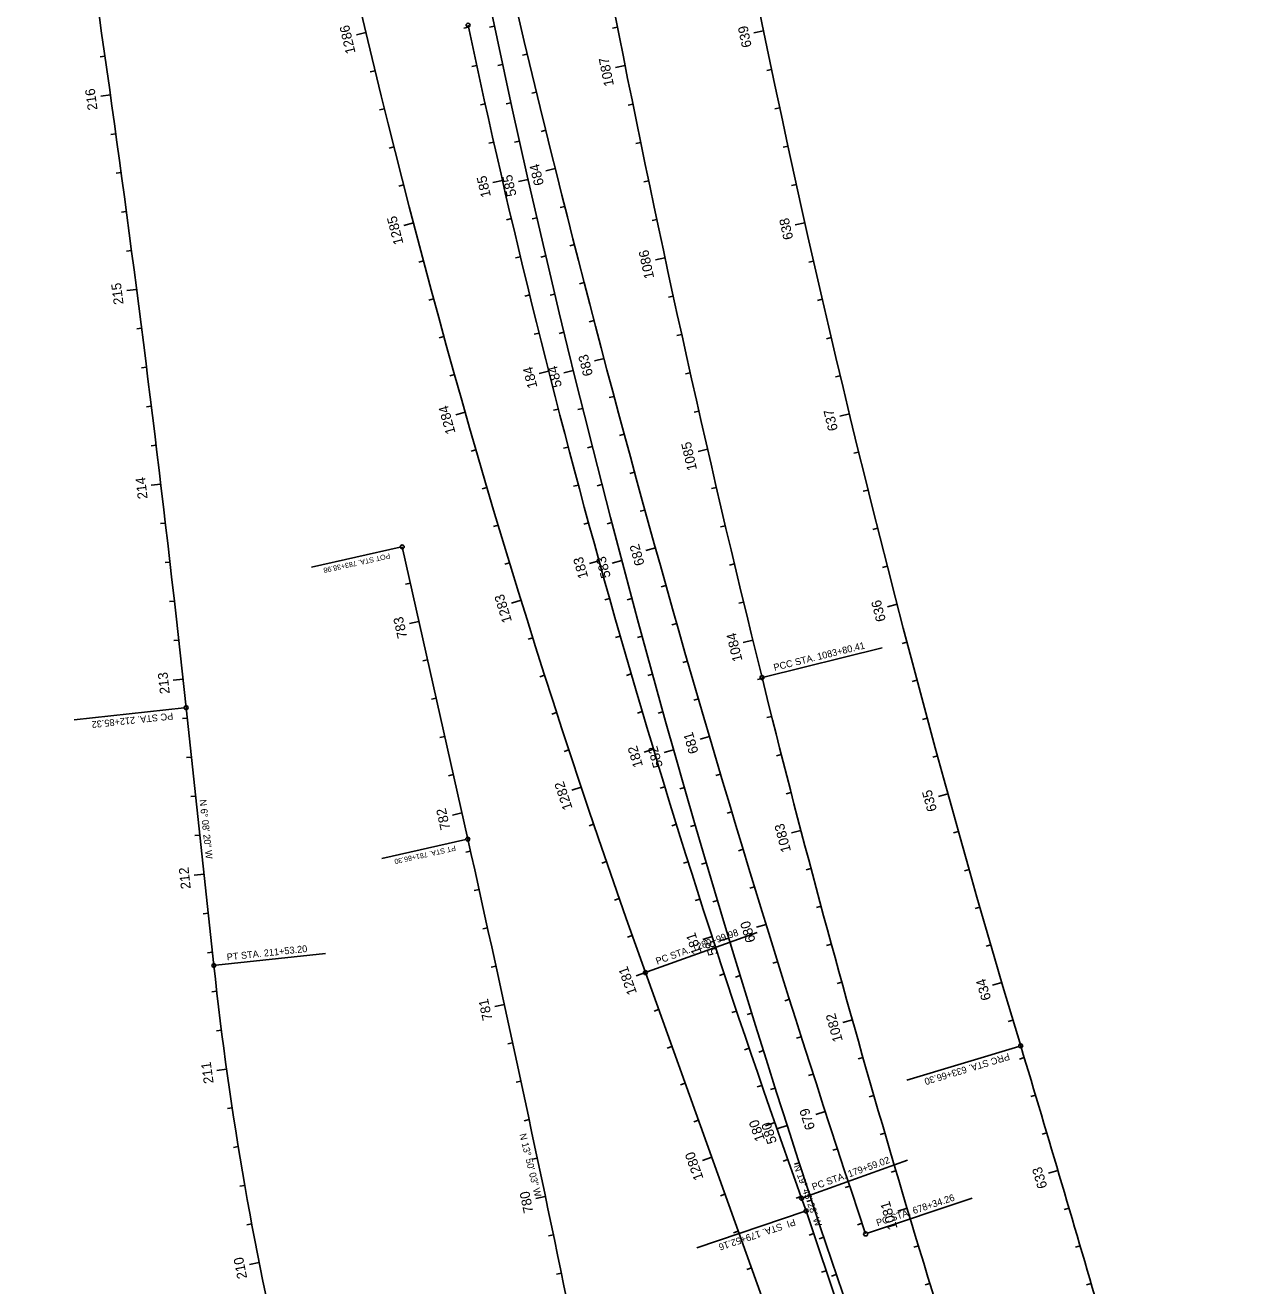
# Model space of a CAD drawing. Extents: x 919452 to 931278, y 583254 to 665650.
# Drawn here: x 928872 to 929495, y 633795 to 634438 of the extents above; entities that cross this region are included whole.
import ezdxf

# ---------------------------------------------------------------- set-up
doc = ezdxf.new("R2010")
doc.units = 0
for name, color, linetype in [('LaneLine', 7, 'Continuous'), ('PMStripe24W', 7, 'Continuous'), ('Scratch1_dp', 7, 'Continuous'), ('ScratchEle_dp', 7, 'Continuous'), ('ShldrHatch', 7, 'Continuous'), ('TollReader', 7, 'Continuous')]:
    doc.layers.add(name, color=color, linetype=linetype)

msp = doc.modelspace()

# ---------------------------------------------------------------- linework, layer by layer
at = {"layer": 'LaneLine'}
for p, q in [((929062.78, 634171.8), (929017.59, 634161.67)), ((929248.09, 634105.64), (929308.42, 634120.55)), ((928952.62, 634089.95), (928896.6, 634083.93)), ((929096.2, 634022.82), (929053.39, 634013.22)), ((929188.64, 633955.42), (929244.61, 633975.53)), ((928968.74, 633958.81), (929024.58, 633964.82)), ((929378.01, 633917.45), (929320.85, 633900.23)), ((929268.22, 633840.38), (929321.24, 633859.43)), ((929300.87, 633822.18), (929354.24, 633840.03)), ((929268.64, 633833.27), (929213.95, 633814.85))]:
    msp.add_line(p, q, dxfattribs=at)
for centre in [(929097.32, 634437.85), (929063.76, 634172.02), (929247.12, 634105.4), (928953.61, 634090.06), (929097.18, 634023.04), (928967.74, 633958.7), (929187.7, 633955.08), (929378.97, 633917.74), (929267.27, 633840.04), (929269.59, 633833.59), (929299.93, 633821.86)]:
    msp.add_circle(centre, 1, dxfattribs=at)
at = {"layer": 'Scratch1_dp'}
for p, q in [((929097.52, 634436.88), (929095.08, 634436.36)), ((929110.71, 634437.39), (929108.26, 634436.87)), ((929173.43, 634436.86), (929170.97, 634436.38)), ((928912.23, 634422.16), (928909.76, 634421.81)), ((929127.49, 634423.17), (929125.06, 634422.59)), ((929049.93, 634414.67), (929047.5, 634414.09)), ((929101.72, 634417.33), (929099.28, 634416.8)), ((929114.9, 634417.83), (929112.46, 634417.3)), ((929252.02, 634415.35), (929249.57, 634414.84)), ((929132.19, 634403.73), (929129.76, 634403.14)), ((929054.68, 634395.25), (929052.25, 634394.65)), ((929106.01, 634397.79), (929103.57, 634397.25)), ((929119.17, 634398.29), (929116.73, 634397.76)), ((929181.29, 634397.65), (929178.84, 634397.15)), ((929256.16, 634395.78), (929253.71, 634395.26)), ((928917.77, 634382.54), (928915.29, 634382.2)), ((929136.94, 634384.3), (929134.51, 634383.71)), ((929059.52, 634375.84), (929057.09, 634375.23)), ((929110.38, 634378.27), (929107.94, 634377.72)), ((929123.5, 634378.77), (929121.06, 634378.22)), ((929185.31, 634378.05), (929182.86, 634377.55)), ((929260.37, 634376.23), (929257.92, 634375.7)), ((928920.47, 634362.73), (928918, 634362.39)), ((929064.44, 634356.46), (929062.02, 634355.84)), ((929189.38, 634358.47), (929186.93, 634357.96)), ((929264.64, 634356.69), (929262.2, 634356.15)), ((928923.14, 634342.9), (928920.66, 634342.57)), ((929146.61, 634345.49), (929144.19, 634344.88)), ((929119.37, 634339.3), (929116.94, 634338.73)), ((929132.38, 634339.77), (929129.94, 634339.2)), ((929193.5, 634338.9), (929191.06, 634338.38)), ((928925.77, 634323.08), (928923.29, 634322.75)), ((929151.53, 634326.1), (929149.1, 634325.49)), ((929074.55, 634317.76), (929072.14, 634317.11)), ((929124, 634319.84), (929121.57, 634319.26)), ((929136.91, 634320.29), (929134.48, 634319.72)), ((929273.38, 634317.66), (929270.94, 634317.1)), ((929156.5, 634306.73), (929154.08, 634306.11)), ((929079.74, 634298.44), (929077.33, 634297.79)), ((929128.71, 634300.4), (929126.28, 634299.81)), ((929141.52, 634300.83), (929139.09, 634300.25)), ((929201.91, 634299.8), (929199.47, 634299.26)), ((929277.85, 634298.16), (929275.41, 634297.6)), ((929161.52, 634287.37), (929159.1, 634286.74)), ((928930.9, 634283.41), (928928.42, 634283.09)), ((929085.01, 634279.15), (929082.6, 634278.48)), ((929133.5, 634280.99), (929131.08, 634280.38)), ((929146.19, 634281.38), (929143.76, 634280.79)), ((929206.2, 634280.26), (929203.76, 634279.72)), ((929282.38, 634278.69), (929279.95, 634278.11)), ((928933.41, 634263.57), (928930.93, 634263.26)), ((929090.37, 634259.88), (929087.96, 634259.2)), ((929210.54, 634260.74), (929208.1, 634260.19)), ((929286.98, 634259.22), (929284.55, 634258.64)), ((929171.73, 634248.7), (929169.31, 634248.05)), ((928935.88, 634243.72), (928933.4, 634243.41)), ((929143.34, 634242.22), (929140.92, 634241.59)), ((929155.75, 634242.54), (929153.32, 634241.93)), ((929214.94, 634241.23), (929212.5, 634240.67)), ((929176.91, 634229.38), (929174.5, 634228.73)), ((928938.31, 634223.87), (928935.82, 634223.57)), ((929101.34, 634221.41), (929098.94, 634220.71)), ((929148.39, 634222.86), (929145.97, 634222.23)), ((929160.62, 634223.14), (929158.2, 634222.53)), ((929296.37, 634220.34), (929293.94, 634219.74)), ((929182.15, 634210.08), (929179.74, 634209.42)), ((929106.95, 634202.22), (929104.55, 634201.51)), ((929153.53, 634203.53), (929151.11, 634202.89)), ((929165.57, 634203.76), (929163.15, 634203.14)), ((929223.89, 634202.24), (929221.46, 634201.68)), ((929301.16, 634200.92), (929298.74, 634200.32)), ((929187.44, 634190.79), (929185.03, 634190.13)), ((928943.04, 634184.15), (928940.56, 634183.86)), ((929112.65, 634183.04), (929110.26, 634182.33)), ((929158.74, 634184.23), (929156.33, 634183.57)), ((929170.58, 634184.4), (929168.16, 634183.77)), ((929228.45, 634182.77), (929226.02, 634182.19)), ((929306.02, 634181.52), (929303.6, 634180.91)), ((928945.35, 634164.28), (928942.87, 634164)), ((929118.44, 634163.9), (929116.05, 634163.17)), ((929233.06, 634163.31), (929230.63, 634162.73)), ((929310.94, 634162.14), (929308.52, 634161.52)), ((929067.91, 634153.5), (929065.48, 634152.95)), ((929198.18, 634152.26), (929195.78, 634151.58)), ((928947.62, 634144.41), (928945.13, 634144.13)), ((929169.43, 634145.68), (929167.02, 634145)), ((929180.81, 634145.73), (929178.4, 634145.08)), ((929237.73, 634143.86), (929235.3, 634143.27)), ((929203.64, 634133.02), (929201.23, 634132.33)), ((928949.85, 634124.54), (928947.36, 634124.26)), ((929130.26, 634125.69), (929127.88, 634124.94)), ((929174.9, 634126.44), (929172.49, 634125.75)), ((929186.03, 634126.42), (929183.61, 634125.77)), ((929320.98, 634123.42), (929318.56, 634122.78)), ((929076.67, 634114.47), (929074.23, 634113.92)), ((929209.14, 634113.79), (929206.74, 634113.1)), ((929136.31, 634106.62), (929133.93, 634105.86)), ((929180.45, 634107.23), (929178.05, 634106.53)), ((929191.31, 634107.13), (929188.9, 634106.47)), ((929247.22, 634105), (929244.79, 634104.4)), ((929326.1, 634104.08), (929323.68, 634103.44)), ((929081.05, 634094.95), (929078.61, 634094.41)), ((929214.7, 634094.58), (929212.3, 634093.88)), ((929142.43, 634087.58), (929140.06, 634086.81)), ((929186.09, 634088.04), (929183.69, 634087.33)), ((929196.66, 634087.86), (929194.25, 634087.19)), ((929252.05, 634085.59), (929249.63, 634084.99)), ((928954.18, 634084.77), (928951.7, 634084.5)), ((929331.28, 634084.76), (929328.86, 634084.11)), ((929085.42, 634075.44), (929082.99, 634074.89)), ((929148.64, 634068.57), (929146.27, 634067.79)), ((929256.96, 634066.2), (929254.53, 634065.59)), ((928956.32, 634064.89), (928953.84, 634064.62)), ((929336.52, 634065.46), (929334.11, 634064.8)), ((929089.8, 634055.92), (929087.36, 634055.38)), ((929225.98, 634056.2), (929223.58, 634055.49)), ((929197.61, 634049.74), (929195.22, 634049.01)), ((929207.56, 634049.38), (929205.16, 634048.69)), ((929261.93, 634046.83), (929259.51, 634046.21)), ((928958.46, 634045), (928955.97, 634044.73)), ((929231.7, 634037.04), (929229.3, 634036.32)), ((929161.32, 634030.64), (929158.96, 634029.83)), ((929203.5, 634030.62), (929201.11, 634029.88)), ((929213.11, 634030.16), (929210.71, 634029.46)), ((928960.6, 634025.12), (928958.11, 634024.85)), ((929347.2, 634026.92), (929344.8, 634026.24)), ((929098.56, 634016.89), (929096.12, 634016.35)), ((929237.47, 634017.89), (929235.08, 634017.16)), ((929167.79, 634011.71), (929165.42, 634010.9)), ((929209.47, 634011.53), (929207.09, 634010.78)), ((929218.73, 634010.97), (929216.33, 634010.26)), ((929272.07, 634008.14), (929269.65, 634007.5)), ((929352.64, 634007.67), (929350.24, 634006.99)), ((929102.91, 633997.37), (929100.47, 633996.83)), ((929243.3, 633998.76), (929240.9, 633998.02)), ((929174.34, 633992.81), (929171.98, 633991.99)), ((929215.53, 633992.47), (929213.14, 633991.71)), ((929224.41, 633991.79), (929222.02, 633991.08)), ((928964.88, 633985.35), (928962.39, 633985.08)), ((929277.24, 633988.82), (929274.83, 633988.17)), ((929358.14, 633988.44), (929355.74, 633987.75)), ((929107.23, 633977.84), (929104.79, 633977.31)), ((929180.97, 633973.95), (929178.62, 633973.11)), ((928967.02, 633965.46), (928964.53, 633965.19)), ((929282.49, 633969.52), (929280.07, 633968.86)), ((929363.71, 633969.23), (929361.31, 633968.53)), ((929111.53, 633958.31), (929109.09, 633957.78)), ((929255.1, 633960.54), (929252.72, 633959.79)), ((929227.88, 633954.43), (929225.51, 633953.65)), ((929235.99, 633953.5), (929233.6, 633952.77)), ((928969.2, 633945.58), (928966.72, 633945.29)), ((929287.79, 633950.24), (929285.38, 633949.57)), ((929261.09, 633941.45), (929258.7, 633940.7)), ((929194.45, 633936.29), (929192.1, 633935.44)), ((929234.19, 633935.45), (929231.82, 633934.66)), ((929241.87, 633934.39), (929239.48, 633933.65)), ((928971.61, 633925.73), (928969.13, 633925.41)), ((929375.03, 633930.87), (929372.64, 633930.15)), ((929120.03, 633919.23), (929117.59, 633918.7)), ((929267.13, 633922.39), (929264.74, 633921.63)), ((929201.21, 633917.46), (929198.86, 633916.62)), ((929240.57, 633916.5), (929238.21, 633915.69)), ((929247.83, 633915.29), (929245.44, 633914.55)), ((929298.61, 633911.73), (929296.21, 633911.04)), ((929380.78, 633911.71), (929378.39, 633910.99)), ((929124.24, 633899.67), (929121.8, 633899.15)), ((929273.22, 633903.34), (929270.84, 633902.57)), ((929207.97, 633898.64), (929205.62, 633897.79)), ((929247.04, 633897.57), (929244.68, 633896.76)), ((929253.84, 633896.22), (929251.46, 633895.46)), ((929304.12, 633892.5), (929301.72, 633891.81)), ((929386.53, 633892.56), (929384.14, 633891.84)), ((928977.11, 633886.11), (928974.64, 633885.73)), ((929128.42, 633880.12), (929125.98, 633879.59)), ((929214.74, 633879.82), (929212.38, 633878.97)), ((929309.7, 633873.29), (929307.3, 633872.59)), ((929392.25, 633873.39), (929389.85, 633872.68)), ((928980.2, 633866.35), (928977.73, 633865.95)), ((929132.57, 633860.55), (929130.13, 633860.03)), ((929285.56, 633865.29), (929283.18, 633864.51)), ((929260.23, 633859.81), (929257.87, 633858.97)), ((929266.08, 633858.14), (929263.71, 633857.37)), ((929315.34, 633854.11), (929312.95, 633853.4)), ((928983.52, 633846.62), (928981.06, 633846.2)), ((929228.26, 633842.17), (929225.9, 633841.33)), ((929291.81, 633846.29), (929289.43, 633845.51)), ((929266.94, 633840.97), (929264.59, 633840.12)), ((929272.3, 633839.13), (929269.93, 633838.35)), ((929403.6, 633835.04), (929401.2, 633834.33)), ((928987.07, 633826.94), (928984.61, 633826.48)), ((929235.02, 633823.35), (929232.67, 633822.5)), ((929273.47, 633822.07), (929271.1, 633821.27)), ((929298.11, 633827.31), (929295.74, 633826.52)), ((929140.79, 633821.4), (929138.34, 633820.89)), ((929278.59, 633820.14), (929276.21, 633819.35)), ((929326.83, 633815.79), (929324.44, 633815.07)), ((929409.23, 633815.84), (929406.83, 633815.14)), ((929241.78, 633804.53), (929239.43, 633803.68)), ((929279.86, 633803.11), (929277.49, 633802.31)), ((929144.85, 633801.82), (929142.4, 633801.31)), ((929284.94, 633801.18), (929282.57, 633800.38)), ((929332.68, 633796.67), (929330.29, 633795.93)), ((929414.83, 633796.65), (929412.43, 633795.95))]:
    msp.add_line(p, q, dxfattribs=at)
at = {"layer": 'ScratchEle_dp'}
for p, q in [((929097.18, 634023.04), (929063.76, 634172.02)), ((928967.74, 633958.7), (928953.61, 634090.06)), ((929494.71, 633100.38), (929187.7, 633955.08)), ((929269.59, 633833.59), (929267.27, 633840.04)), ((929461.08, 633264.99), (929269.59, 633833.59))]:
    msp.add_line(p, q, dxfattribs=at)
for centre, radius, start, end in [((934714.76, 635630.15), 5729.58, 175.955434, 198.89818), ((935122.08, 635647.98), 5998.08, 187.109635, 196.766064), ((933402.41, 635468.98), 4478.35, 187.81416, 199.75791), ((936244.12, 635835), 7207.6, 188.199151, 193.884708), ((919061.67, 633026.13), 9949, 6.138854, 9.590734), ((936128.21, 636105.39), 7200, 192.636554, 198.491034), ((933581.09, 635389.53), 4583.66, 191.98316, 199.75791), ((934799.58, 635477.92), 5719.58, 193.88471, 198.61214), ((915974, 631079.31), 13449.29, 10.454203, 12.643022), ((930687.21, 634143.64), 1729.38, 186.13885, 201.15388), ((916462.13, 630026.27), 13490.3, 16.142538, 16.766064)]:
    msp.add_arc(centre, radius, start, end, dxfattribs=at)
at = {"layer": 'TollReader'}
for p, q in [((929045.26, 634434.12), (929040.4, 634432.97)), ((929247.94, 634434.93), (929243.04, 634433.92)), ((929177.33, 634417.25), (929172.43, 634416.27)), ((928915.02, 634402.35), (928910.07, 634401.66)), ((929141.75, 634364.89), (929136.9, 634363.68)), ((929114.83, 634358.78), (929109.96, 634357.65)), ((929127.91, 634359.26), (929123.03, 634358.15)), ((929069.46, 634337.09), (929064.62, 634335.83)), ((929268.98, 634337.17), (929264.1, 634336.08)), ((929197.68, 634319.34), (929192.79, 634318.29)), ((928928.36, 634303.25), (928923.4, 634302.6)), ((929166.6, 634268.03), (929161.76, 634266.75)), ((929138.38, 634261.59), (929133.53, 634260.36)), ((929150.94, 634261.95), (929146.08, 634260.76)), ((929095.81, 634240.63), (929091, 634239.26)), ((929291.64, 634239.77), (929286.78, 634238.6)), ((929219.39, 634221.73), (929214.51, 634220.61)), ((928940.69, 634204.01), (928935.73, 634203.42)), ((929192.79, 634171.52), (929187.97, 634170.18)), ((929164.04, 634164.94), (929159.23, 634163.61)), ((929175.66, 634165.06), (929170.83, 634163.78)), ((929124.31, 634144.78), (929119.53, 634143.3)), ((929315.93, 634142.77), (929311.09, 634141.51)), ((929072.29, 634133.98), (929067.41, 634132.89)), ((929242.45, 634124.42), (929237.59, 634123.24)), ((928952.03, 634104.66), (928947.06, 634104.11)), ((929220.31, 634075.38), (929215.52, 634073.97)), ((929191.81, 634068.88), (929187.02, 634067.44)), ((929202.07, 634068.61), (929197.26, 634067.25)), ((929154.94, 634049.59), (929150.2, 634048.01)), ((929341.83, 634046.18), (929337.01, 634044.85)), ((929094.18, 634036.41), (929089.3, 634035.31)), ((929266.97, 634027.48), (929262.13, 634026.21)), ((928962.74, 634005.23), (928957.77, 634004.7)), ((929249.17, 633979.64), (929244.4, 633978.16)), ((929221.66, 633973.44), (929216.91, 633971.89)), ((929230.17, 633972.64), (929225.38, 633971.19)), ((929187.69, 633955.11), (929182.99, 633953.42)), ((929369.34, 633950.04), (929364.54, 633948.62)), ((929115.8, 633938.77), (929110.91, 633937.71)), ((929293.17, 633930.97), (929288.36, 633929.62)), ((928974.24, 633905.9), (928969.29, 633905.21)), ((929279.36, 633884.3), (929274.6, 633882.76)), ((929253.59, 633878.67), (929248.87, 633877.03)), ((929259.93, 633877.17), (929255.17, 633875.64)), ((929221.5, 633860.99), (929216.79, 633859.3)), ((929397.94, 633854.22), (929393.14, 633852.8)), ((929136.69, 633840.98), (929131.8, 633839.95)), ((929321.06, 633834.94), (929316.27, 633833.5)), ((928990.85, 633807.3), (928985.94, 633806.33))]:
    msp.add_line(p, q, dxfattribs=at)

# ---------------------------------------------------------------- texts
at = {"layer": 'LaneLine'}
for s, height, rotation, p in [('POT STA. 783+38.98', 2.625, 192.64302, (929057.31, 634168.78)), ('PCC STA. 1083+80.41', 3.5, 13.88471, (929253.5, 634108.78)), ('PC STA. 212+85.32', 3.5, 186.13885, (928946.84, 634087.57)), ('PT STA. 781+86.30', 2.625, 192.64302, (929090.73, 634019.8)), ('PC STA. 1280+99.98', 3.5, 19.75791, (929193.7, 633959.1)), ('PT STA. 211+53.20', 3.5, 6.13885, (928974.52, 633961.19)), ('PRC STA. 633+66.30', 3.5, 196.76606, (929372.77, 633914.05)), ('PC STA. 179+59.02', 3.5, 19.75791, (929273.27, 633844.06)), ('PC STA. 678+34.26', 3.5, 18.49103, (929306.01, 633825.74)), ('PI  STA. 179+52.16', 3.5, 198.61187, (929263.52, 633829.7))]:
    msp.add_text(s, height=height, rotation=rotation, dxfattribs=at).set_placement(p)
at = {"layer": 'PMStripe24W'}
for s, rotation, p in [('N 6%%d 08\' 20" W', 276.13885, (928960.43, 634043.09)), ('N 13%%d 50\' 03" W', 283.8342, (929123.46, 633872.61)), ('N 19%%d 45\' 28" W', 289.75791, (929263.25, 633856.41))]:
    msp.add_text(s, height=3.5, rotation=rotation, dxfattribs=at).set_placement(p)
at = {"layer": 'ShldrHatch'}
for s, rotation, p in [('1286', 103.36063, (929040, 634423.85)), ('639', 101.66794, (929241.91, 634427.01)), ('1087', 101.34417, (929171.69, 634407.23)), ('216', 97.95109, (928908.5, 634394.84)), ('585', 102.81552, (929122.05, 634351.19)), ('684', 103.98902, (929136.04, 634356.78)), ('185', 102.9956, (929109, 634350.69)), ('1285', 104.64002, (929064.43, 634326.67)), ('638', 102.62318, (929263.09, 634329.12)), ('1086', 102.1391, (929192.2, 634309.18)), ('215', 97.37519, (928921.76, 634295.77)), ('683', 104.78479, (929161.03, 634259.74)), ('184', 104.2456, (929132.71, 634253.46)), ('584', 103.81552, (929145.2, 634253.86)), ('1284', 105.91941, (929090.99, 634230.18)), ('637', 103.57841, (929285.87, 634231.72)), ('1085', 102.93404, (929214.05, 634211.46)), ('214', 96.7993, (928934.01, 634196.68)), ('682', 105.58057, (929187.33, 634163.16)), ('183', 105.4956, (929158.58, 634156.59)), ('583', 104.81552, (929170.1, 634156.77)), ('1283', 107.19881, (929119.76, 634134.12)), ('636', 104.53365, (929310.31, 634134.56)), ('783', 102.64302, (929066.42, 634125.91)), ('1084', 103.72898, (929237.23, 634114.16)), ('213', 96.2234, (928945.29, 634097.29)), ('681', 106.37634, (929214.85, 634067.38)), ('182', 106.7456, (929186.52, 634060.41)), ('582', 105.81552, (929196.65, 634060.23)), ('1282', 108.4782, (929150.63, 634038.84)), ('635', 105.48888, (929336.36, 634037.85)), ('782', 102.64302, (929088.3, 634028.34)), ('1083', 104.69021, (929261.95, 634017.03)), ('212', 96.13885, (928955.99, 633997.88)), ('680', 107.17212, (929243.93, 633971.19)), ('181', 107.9956, (929216.43, 633965.29)), ('581', 106.81552, (929224.76, 633964.59)), ('1281', 109.7576, (929183.47, 633944.69)), ('634', 106.44411, (929363.98, 633941.7)), ('781', 102.27537, (929109.77, 633931.18)), ('1082', 105.69196, (929288.34, 633920.44)), ('211', 97.90155, (928967.66, 633898.79)), ('180', 109.2456, (929248.66, 633870.04)), ('679', 107.96789, (929274.24, 633875.78)), ('580', 107.81551, (929254.79, 633868.66)), ('1280', 109.75791, (929217.4, 633850.21)), ('633', 106.48449, (929392.62, 633845.77)), ('780', 101.84936, (929130.69, 633833.06)), ('1081', 106.6937, (929316.28, 633824.76)), ('210', 101.21464, (928984.76, 633799.44))]:
    msp.add_text(s, height=5, rotation=rotation, dxfattribs=at).set_placement(p)

doc.saveas('drawing.dxf')
